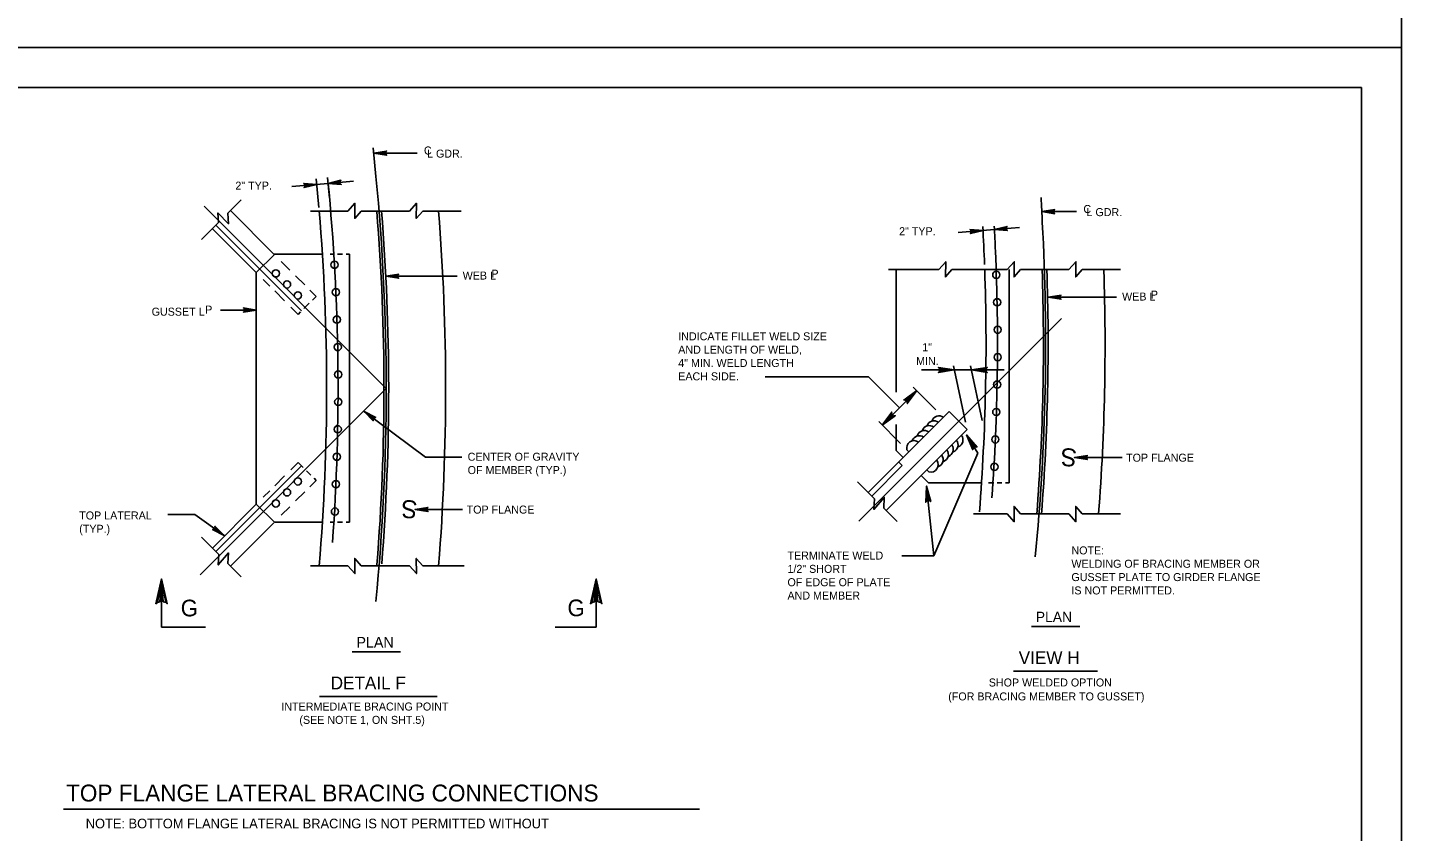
# Model space of a CAD drawing. Extents: x 30 to 2621, y -33 to 1155.
# Drawn here: x 2038 to 2553, y 267 to 569 of the extents above; entities that cross this region are included whole.
import ezdxf

# ---------------------------------------------------------------- set-up
doc = ezdxf.new("R2010")
doc.units = 0
doc.layers.add('1', color=7, linetype='Continuous')
doc.layers.add('PLT-BNDY', color=7, linetype='Continuous')

msp = doc.modelspace()

# ---------------------------------------------------------------- linework, layer by layer
at = {"layer": '1'}
for p, q in [((2538.5, 546), (1752.5, 546)), ((2538.5, -18), (2538.5, 546)), ((2169.07, 512.65), (2168.07, 523.39)), ((2168.25, 521.44), (2184.5, 521.44)), ((2137.58, 508.92), (2151.17, 510.09)), ((2147.67, 501.1), (2146.67, 511.84)), ((2151.68, 504.61), (2150.96, 512.3)), ((2151.17, 510.09), (2160.64, 510.9)), ((2104.7, 501.51), (2172.94, 433.28)), ((2113.59, 498.9), (2118.58, 503.9)), ((2114.56, 499.88), (2130.83, 483.61)), ((2144.6, 499.7), (2158.55, 499.7)), ((2163.53, 499.7), (2181.65, 499.7)), ((2186.63, 499.7), (2200.99, 499.7)), ((2103.73, 489.04), (2110.06, 495.38)), ((2418.66, 499.52), (2431.68, 499.52)), ((2107.8, 493.12), (2124.24, 476.68)), ((2109.1, 494.41), (2141.21, 462.31)), ((2387.31, 491.64), (2400.9, 492.8)), ((2400.9, 492.8), (2410.37, 493.61)), ((2124.24, 476.68), (2131, 483.44)), ((2130.83, 483.61), (2148.99, 483.61)), ((2133.61, 480.83), (2136.82, 477.62)), ((2151.89, 483.61), (2153.49, 483.61)), ((2151.89, 483.61), (2153.49, 483.61)), ((2156.53, 483.61), (2154.72, 483.61)), ((2156.53, 483.61), (2154.72, 483.61)), ((2157.94, 483.61), (2159.22, 483.61)), ((2159.22, 483.61), (2159.22, 383.12)), ((2124.24, 389.88), (2124.24, 476.68)), ((2126.85, 474.07), (2129.29, 471.63)), ((2138.97, 475.47), (2142.37, 472.07)), ((2172.77, 475.3), (2199.48, 475.3)), ((2361.24, 477.78), (2380.01, 477.78)), ((2364.05, 431.84), (2364.05, 477.78)), ((2384.99, 477.78), (2405.72, 477.78)), ((2406.4, 477.78), (2406.4, 397.91)), ((2410.71, 477.78), (2428.82, 477.78)), ((2433.81, 477.78), (2448.17, 477.78)), ((2131.13, 469.79), (2134.82, 466.1)), ((2144.34, 470.1), (2146.67, 467.77)), ((2137.17, 463.75), (2139.91, 461.01)), ((2142.09, 463.19), (2144.05, 465.15)), ((2145.26, 466.36), (2146.67, 467.77)), ((2421.03, 467.43), (2446.66, 467.43)), ((2110.78, 462.65), (2124.24, 462.65)), ((2139.91, 461.01), (2140.84, 461.94)), ((2350.12, 383.53), (2426.01, 459.42)), ((2373.54, 440.18), (2385.88, 440.18)), ((2390.11, 420.68), (2385.55, 441.71)), ((2385.88, 440.18), (2392.28, 440.18)), ((2396.37, 421.29), (2391.95, 441.71)), ((2392.28, 440.18), (2404.6, 440.18)), ((2103.14, 363.48), (2172.94, 433.28)), ((2314.97, 437.56), (2353.74, 437.56)), ((2365.32, 425.98), (2353.74, 437.56)), ((2370.49, 433.76), (2378.95, 425.3)), ((2371.8, 432.45), (2358.85, 419.51)), ((2164.64, 424.67), (2187.6, 407.49)), ((2353.62, 394.25), (2383.97, 424.59)), ((2383.97, 424.59), (2390.73, 417.83)), ((2357.54, 420.82), (2365.75, 412.61)), ((2360.38, 387.49), (2390.73, 417.83)), ((2364.05, 410.05), (2364.05, 419.71)), ((2394.65, 409.06), (2390.47, 415.87)), ((2187.6, 407.49), (2201.3, 407.49)), ((2364.05, 410.05), (2366.74, 407.36)), ((2368.1, 410.26), (2368.87, 409.49)), ((2378.25, 370.55), (2394.65, 409.06)), ((2430.92, 407.38), (2448.76, 407.38)), ((2109.1, 372.14), (2141.21, 404.25)), ((2137.17, 402.8), (2139.91, 405.55)), ((2139.91, 405.55), (2141.78, 403.67)), ((2143.07, 402.38), (2144.74, 400.72)), ((2354.92, 392.95), (2366.34, 404.37)), ((2365.04, 405.66), (2366.34, 404.37)), ((2375.62, 402.72), (2376.38, 401.97)), ((2131.13, 396.76), (2134.82, 400.46)), ((2144.34, 396.45), (2146.67, 398.79)), ((2145.87, 399.59), (2146.67, 398.79)), ((2349.55, 398.32), (2356.01, 391.86)), ((2373.5, 400.6), (2376.18, 397.91)), ((2375.46, 396.67), (2378.25, 370.55)), ((2396.2, 397.91), (2376.18, 397.91)), ((2398.67, 397.91), (2400.67, 397.91)), ((2403.7, 397.91), (2401.9, 397.91)), ((2405.12, 397.91), (2406.4, 397.91)), ((2126.85, 392.49), (2129.29, 394.92)), ((2138.97, 391.09), (2142.37, 394.48)), ((2107.8, 373.44), (2124.24, 389.88)), ((2124.24, 389.88), (2131, 383.12)), ((2133.61, 385.73), (2136.82, 388.93)), ((2183.74, 387.93), (2201.59, 387.93)), ((2359.41, 388.46), (2364.4, 383.47)), ((2393.04, 386.3), (2405.72, 386.3)), ((2410.71, 386.3), (2428.82, 386.3)), ((2433.81, 386.3), (2448.17, 386.3)), ((2091.12, 386.06), (2101.22, 386.06)), ((2101.22, 386.06), (2112.23, 378.14)), ((2114.56, 366.68), (2130.83, 382.95)), ((2131, 383.12), (2149.02, 383.12)), ((2151.89, 383.12), (2153.49, 383.12)), ((2151.89, 383.12), (2153.49, 383.12)), ((2156.53, 383.12), (2154.72, 383.12)), ((2156.53, 383.12), (2154.72, 383.12)), ((2157.94, 383.12), (2159.22, 383.12)), ((2103.73, 377.51), (2110.19, 371.05)), ((2113.59, 367.65), (2118.58, 362.66)), ((2144.6, 366.85), (2158.55, 366.85)), ((2163.53, 366.85), (2181.65, 366.85)), ((2186.63, 366.85), (2202.12, 366.85)), ((2366.19, 370.55), (2378.25, 370.55)), ((2088.76, 343.81), (2088.76, 361.89)), ((2251.68, 343.81), (2251.68, 361.89)), ((2088.76, 343.81), (2105.24, 343.81)), ((2236.23, 343.81), (2251.68, 343.81)), ((2414.85, 344.05), (2432.94, 344.05)), ((2160.22, 334.6), (2178.32, 334.6)), ((2408.03, 327.32), (2439.54, 327.32)), ((2147.87, 317.86), (2192.02, 317.86)), ((2290.34, 275.64), (2051.97, 275.64))]:
    msp.add_line(p, q, dxfattribs=at)
for points in [[(2172.86, 520.86), (2172.69, 521.2), (2168.25, 521.44), (2172.86, 520.86), (2173.1, 520.66), (2168.25, 521.44), (2172.68, 521.66), (2172.85, 521.99), (2168.25, 521.44), (2173.1, 522.21), (2172.85, 521.99)], [(2142.26, 509.9), (2142.46, 509.59), (2146.91, 509.72), (2142.26, 509.9), (2142.01, 510.09), (2146.91, 509.72), (2142.51, 509.12), (2142.37, 508.78), (2146.91, 509.72), (2142.14, 508.54), (2142.37, 508.78)], [(2155.81, 509.9), (2155.61, 510.22), (2151.17, 510.09), (2155.81, 509.9), (2156.07, 509.72), (2151.17, 510.09), (2155.57, 510.68), (2155.7, 511.02), (2151.17, 510.09), (2155.93, 511.27), (2155.7, 511.02)], [(2163.53, 499.7), (2161.11, 496.96), (2161.18, 502.67), (2158.55, 499.7)], [(2186.63, 499.7), (2184.21, 496.96), (2184.28, 502.67), (2181.65, 499.7)], [(2423.27, 498.94), (2423.1, 499.28), (2418.66, 499.52), (2423.27, 498.94), (2423.51, 498.74), (2418.66, 499.52), (2423.1, 499.74), (2423.26, 500.07), (2418.66, 499.52), (2423.51, 500.29), (2423.26, 500.07)], [(2110.06, 495.38), (2109.84, 499.03), (2113.82, 494.94), (2113.59, 498.9)], [(2392, 492.62), (2392.2, 492.3), (2396.64, 492.44), (2392, 492.62), (2391.74, 492.8), (2396.64, 492.44), (2392.24, 491.84), (2392.11, 491.5), (2396.64, 492.44), (2391.88, 491.26), (2392.11, 491.5)], [(2405.55, 492.62), (2405.35, 492.94), (2400.9, 492.8), (2405.55, 492.62), (2405.8, 492.44), (2400.9, 492.8), (2405.3, 493.4), (2405.44, 493.74), (2400.9, 492.8), (2405.67, 493.98), (2405.44, 493.74)], [(2384.99, 477.78), (2382.57, 475.04), (2382.65, 480.75), (2380.01, 477.78)], [(2410.71, 477.78), (2408.29, 475.04), (2408.36, 480.75), (2405.72, 477.78)], [(2433.81, 477.78), (2431.38, 475.04), (2431.46, 480.75), (2428.82, 477.78)], [(2177.38, 474.72), (2177.21, 475.05), (2172.77, 475.3), (2177.38, 474.72), (2177.62, 474.52), (2172.77, 475.3), (2177.21, 475.52), (2177.37, 475.85), (2172.77, 475.3), (2177.62, 476.07), (2177.37, 475.85)], [(2425.64, 466.85), (2425.47, 467.19), (2421.03, 467.43), (2425.64, 466.85), (2425.88, 466.65), (2421.03, 467.43), (2425.47, 467.65), (2425.63, 467.98), (2421.03, 467.43), (2425.88, 468.2), (2425.63, 467.98)], [(2119.63, 463.23), (2119.8, 462.9), (2124.24, 462.65), (2119.63, 463.23), (2119.39, 463.43), (2124.24, 462.65), (2119.81, 462.43), (2119.64, 462.1), (2124.24, 462.65), (2119.39, 461.88), (2119.64, 462.1)], [(2380.21, 440.89), (2380.42, 440.48), (2385.88, 440.18), (2380.21, 440.89), (2379.92, 441.14), (2385.88, 440.18), (2380.42, 439.91), (2380.22, 439.5), (2385.88, 440.18), (2379.92, 439.23), (2380.22, 439.5)], [(2397.95, 439.46), (2397.74, 439.88), (2392.28, 440.18), (2397.95, 439.46), (2398.24, 439.22), (2392.28, 440.18), (2397.74, 440.45), (2397.94, 440.85), (2392.28, 440.18), (2398.24, 441.13), (2397.94, 440.85)], [(2367.28, 428.94), (2367.72, 428.8), (2371.8, 432.45), (2367.28, 428.94), (2366.9, 428.91), (2371.8, 432.45), (2368.13, 428.4), (2368.27, 427.97), (2371.8, 432.45), (2368.25, 427.56), (2368.27, 427.97)], [(2167.99, 421.44), (2168.05, 421.81), (2164.64, 424.67), (2167.99, 421.44), (2168.05, 421.14), (2164.64, 424.67), (2168.32, 422.18), (2168.65, 422.35), (2164.64, 424.67), (2168.98, 422.38), (2168.65, 422.35)], [(2363.37, 423.02), (2362.93, 423.16), (2358.85, 419.51), (2363.37, 423.02), (2363.75, 423.05), (2358.85, 419.51), (2362.52, 423.56), (2362.37, 423.99), (2358.85, 419.51), (2362.4, 424.4), (2362.37, 423.99)], [(2392.83, 410.66), (2393.07, 411.06), (2390.47, 415.87), (2392.83, 410.66), (2392.77, 410.29), (2390.47, 415.87), (2393.56, 411.36), (2394.01, 411.41), (2390.47, 415.87), (2394.4, 411.29), (2394.01, 411.41)], [(2435.53, 406.8), (2435.36, 407.13), (2430.92, 407.38), (2435.53, 406.8), (2435.77, 406.6), (2430.92, 407.38), (2435.36, 407.6), (2435.52, 407.93), (2430.92, 407.38), (2435.77, 408.15), (2435.52, 407.93)], [(2375.35, 390.95), (2375.74, 391.2), (2375.46, 396.67), (2375.35, 390.95), (2375.14, 390.63), (2375.46, 396.67), (2376.31, 391.27), (2376.73, 391.11), (2375.46, 396.67), (2377.04, 390.84), (2376.73, 391.11)], [(2356.01, 391.86), (2355.77, 387.96), (2359.64, 392.42), (2359.41, 388.46)], [(2188.36, 387.35), (2188.19, 387.69), (2183.74, 387.93), (2188.36, 387.35), (2188.59, 387.15), (2183.74, 387.93), (2188.18, 388.15), (2188.34, 388.48), (2183.74, 387.93), (2188.59, 388.7), (2188.34, 388.48)], [(2410.71, 386.3), (2408.29, 389.04), (2408.36, 383.33), (2405.72, 386.3)], [(2433.81, 386.3), (2431.38, 389.04), (2431.46, 383.33), (2428.82, 386.3)], [(2108.82, 381.31), (2108.77, 380.93), (2112.23, 378.14), (2108.82, 381.31), (2108.75, 381.61), (2112.23, 378.14), (2108.5, 380.55), (2108.17, 380.38), (2112.23, 378.14), (2107.84, 380.35), (2108.17, 380.38)], [(2110.19, 371.05), (2109.95, 367.15), (2113.82, 371.61), (2113.59, 367.65)], [(2163.53, 366.85), (2161.11, 369.59), (2161.18, 363.89), (2158.55, 366.85)], [(2186.63, 366.85), (2184.21, 369.59), (2184.28, 363.89), (2181.65, 366.85)], [(2087.15, 353.03), (2088.08, 353.36), (2088.76, 361.89), (2087.15, 353.03), (2086.6, 352.58), (2088.76, 361.89), (2089.36, 353.37), (2090.28, 353.06), (2088.76, 361.89), (2090.89, 352.58), (2090.28, 353.06)], [(2250.08, 353.03), (2251.01, 353.36), (2251.68, 361.89), (2250.08, 353.03), (2249.52, 352.58), (2251.68, 361.89), (2252.29, 353.37), (2253.2, 353.06), (2251.68, 361.89), (2253.81, 352.58), (2253.2, 353.06)]]:
    msp.add_lwpolyline(points, dxfattribs=at)
for centre in [(2153.56, 479.61), (2131.57, 476.38), (2401.6, 475.81), (2135.76, 472.23), (2139.83, 468.12), (2154.08, 469.33), (2401.95, 465.54), (2154.43, 459.05), (2402.12, 455.26), (2154.78, 448.78), (2402.12, 444.98), (2154.95, 438.5), (2401.95, 434.71), (2154.95, 428.22), (2401.6, 424.43), (2154.78, 417.95), (2401.25, 414.16), (2154.43, 407.67), (2400.91, 403.88), (2139.83, 398.43), (2154.08, 397.39), (2131.57, 390.18), (2135.76, 394.32), (2153.73, 387.12)]:
    msp.add_circle(centre, 1.35, dxfattribs=at)
for centre, radius, start, end in [((1353.05, 433.12), 801.83, 355.88126, 5.56644), ((1353.05, 433.12), 819.89, 354.42094, 5.56644), ((1617.78, 460.58), 801.83, 2.49008, 3.1629), ((1353.05, 433.12), 797.54, 355.23373, 4.79617), ((1353.05, 433.12), 819.05, 355.38412, 4.66297), ((1353.05, 433.12), 820.81, 355.41582, 4.65295), ((1353.05, 433.12), 842.15, 355.48674, 4.53477), ((1600.22, 449.88), 819.89, 354.42094, 3.18397), ((1600.22, 449.88), 797.54, 2.14068, 3.1629), ((1600.22, 449.88), 801.83, 2.49008, 3.1629), ((1600.22, 449.88), 801.83, 355.88126, 2.49008), ((1600.22, 449.88), 797.54, 355.48393, 2.00181), ((1600.22, 449.88), 819.05, 355.54966, 1.94225), ((1600.22, 449.88), 820.81, 355.55728, 1.95377), ((1600.22, 449.88), 842.15, 355.67937, 1.87763), ((2380.15, 420.19), 2.8, 54.1186, 158.9855), ((2374.66, 414.7), 2.8, 54.1186, 158.9855), ((2376.51, 416.55), 2.8, 54.1186, 158.9855), ((2378.25, 418.35), 2.8, 54.1186, 158.9855), ((2370.82, 410.91), 2.8, 54.1186, 193.4935), ((2372.72, 412.76), 2.8, 54.1186, 158.9855), ((2384.48, 412.12), 2.8, 291.0145, 35.8814), ((2386.33, 414.01), 2.8, 291.0145, 35.8814), ((2378.89, 406.58), 2.8, 291.0145, 35.8814), ((2380.84, 408.53), 2.8, 291.0145, 35.8814), ((2382.68, 410.37), 2.8, 291.0145, 35.8814), ((2377.05, 404.69), 2.8, 256.1794, 35.8814)]:
    msp.add_arc(centre, radius, start, end, dxfattribs=at)
at = {"layer": 'PLT-BNDY'}
for points in [[(1712.5, 1155), (2553.5, 1155), (2553.5, 561), (1712.5, 561)], [(1712.5, 561), (2553.5, 561), (2553.5, -33), (1712.5, -33)]]:
    msp.add_lwpolyline(points, close=True, dxfattribs=at)

# ---------------------------------------------------------------- texts
at = {"layer": '1'}
for s, height, p in [('C', 3, (2187.07, 520.91)), ('L GDR.', 3, (2188.24, 519.74)), ('2" TYP.', 3, (2116.4, 507.75)), ('C', 3, (2434.25, 498.99)), ('L GDR.', 3, (2435.42, 497.82)), ('2" TYP.', 3, (2365.18, 490.67)), ('WEB L', 3, (2201.59, 474.06)), ('P', 3, (2212.36, 474.76)), ('WEB L', 3, (2448.76, 466.2)), ('P', 3, (2459.53, 466.9)), ('GUSSET L', 3, (2085.01, 460.52)), ('P', 3, (2105.08, 461.3)), ('INDICATE FILLET WELD SIZE', 3, (2282.39, 451.29)), ('AND LENGTH OF WELD,', 3, (2282.39, 446.29)), ('1"', 3, (2373.85, 447.21)), ('4" MIN. WELD LENGTH ', 3, (2282.39, 441.29)), ('MIN.', 3, (2371.55, 442.07)), ('EACH SIDE.', 3, (2282.39, 436.29)), ('CENTER OF GRAVITY', 3, (2203.46, 406.18)), ('TOP FLANGE', 3, (2450.26, 405.82)), ('OF MEMBER (TYP.)', 3, (2203.46, 401.18)), ('TOP LATERAL', 3, (2057.86, 384.17)), ('TOP FLANGE', 3, (2203.08, 386.37)), ('(TYP.)', 3, (2057.86, 379.17)), ('TERMINATE WELD', 3, (2323.34, 369.16)), ('NOTE:', 3, (2429.77, 371.08)), ('1/2" SHORT', 3, (2323.34, 364.16)), ('WELDING OF BRACING MEMBER OR', 3, (2429.77, 366.08)), ('OF EDGE OF PLATE', 3, (2323.34, 359.16)), ('GUSSET PLATE TO GIRDER FLANGE', 3, (2429.77, 361.08)), ('AND MEMBER', 3, (2323.34, 354.16)), ('IS NOT PERMITTED.', 3, (2429.77, 356.08)), ('G', 6.24, (2095.9, 347.87)), ('G', 6.24, (2240.86, 347.92)), ('PLAN', 3.9, (2416.4, 345.71)), ('PLAN', 4, (2161.78, 336.15)), ('VIEW H', 4.8, (2410.01, 329.99)), ('DETAIL F', 4.8, (2152.12, 320.53)), ('SHOP WELDED OPTION', 3, (2398.8, 321.59)), ('(FOR BRACING MEMBER TO GUSSET)', 3, (2383.6, 316.37)), ('INTERMEDIATE BRACING POINT', 3, (2133.63, 312.58)), ('(SEE NOTE 1, ON SHT.5)', 3, (2140.39, 307.58)), ('TOP FLANGE LATERAL BRACING CONNECTIONS', 6.336, (2052.92, 278.5)), ('NOTE: BOTTOM FLANGE LATERAL BRACING IS NOT PERMITTED WITHOUT', 3.6, (2060.31, 268.45))]:
    msp.add_text(s, height=height, dxfattribs=at).set_placement(p)
for p in [(2431.98, 410.6), (2184.8, 391.16)]:
    msp.add_text('S', height=6.72, rotation=176.2424, dxfattribs=at).set_placement(p)

doc.saveas('drawing.dxf')
